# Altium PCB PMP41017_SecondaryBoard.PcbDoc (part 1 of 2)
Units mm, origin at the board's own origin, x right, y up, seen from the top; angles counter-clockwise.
Board outline 59.94 x 50.1 mm, 4 copper layers (Top Layer, Layer 1, Layer 2, Bottom Layer), stack 1.926 mm thick; 120 components, 60 nets, 831 pads, 509 vias.
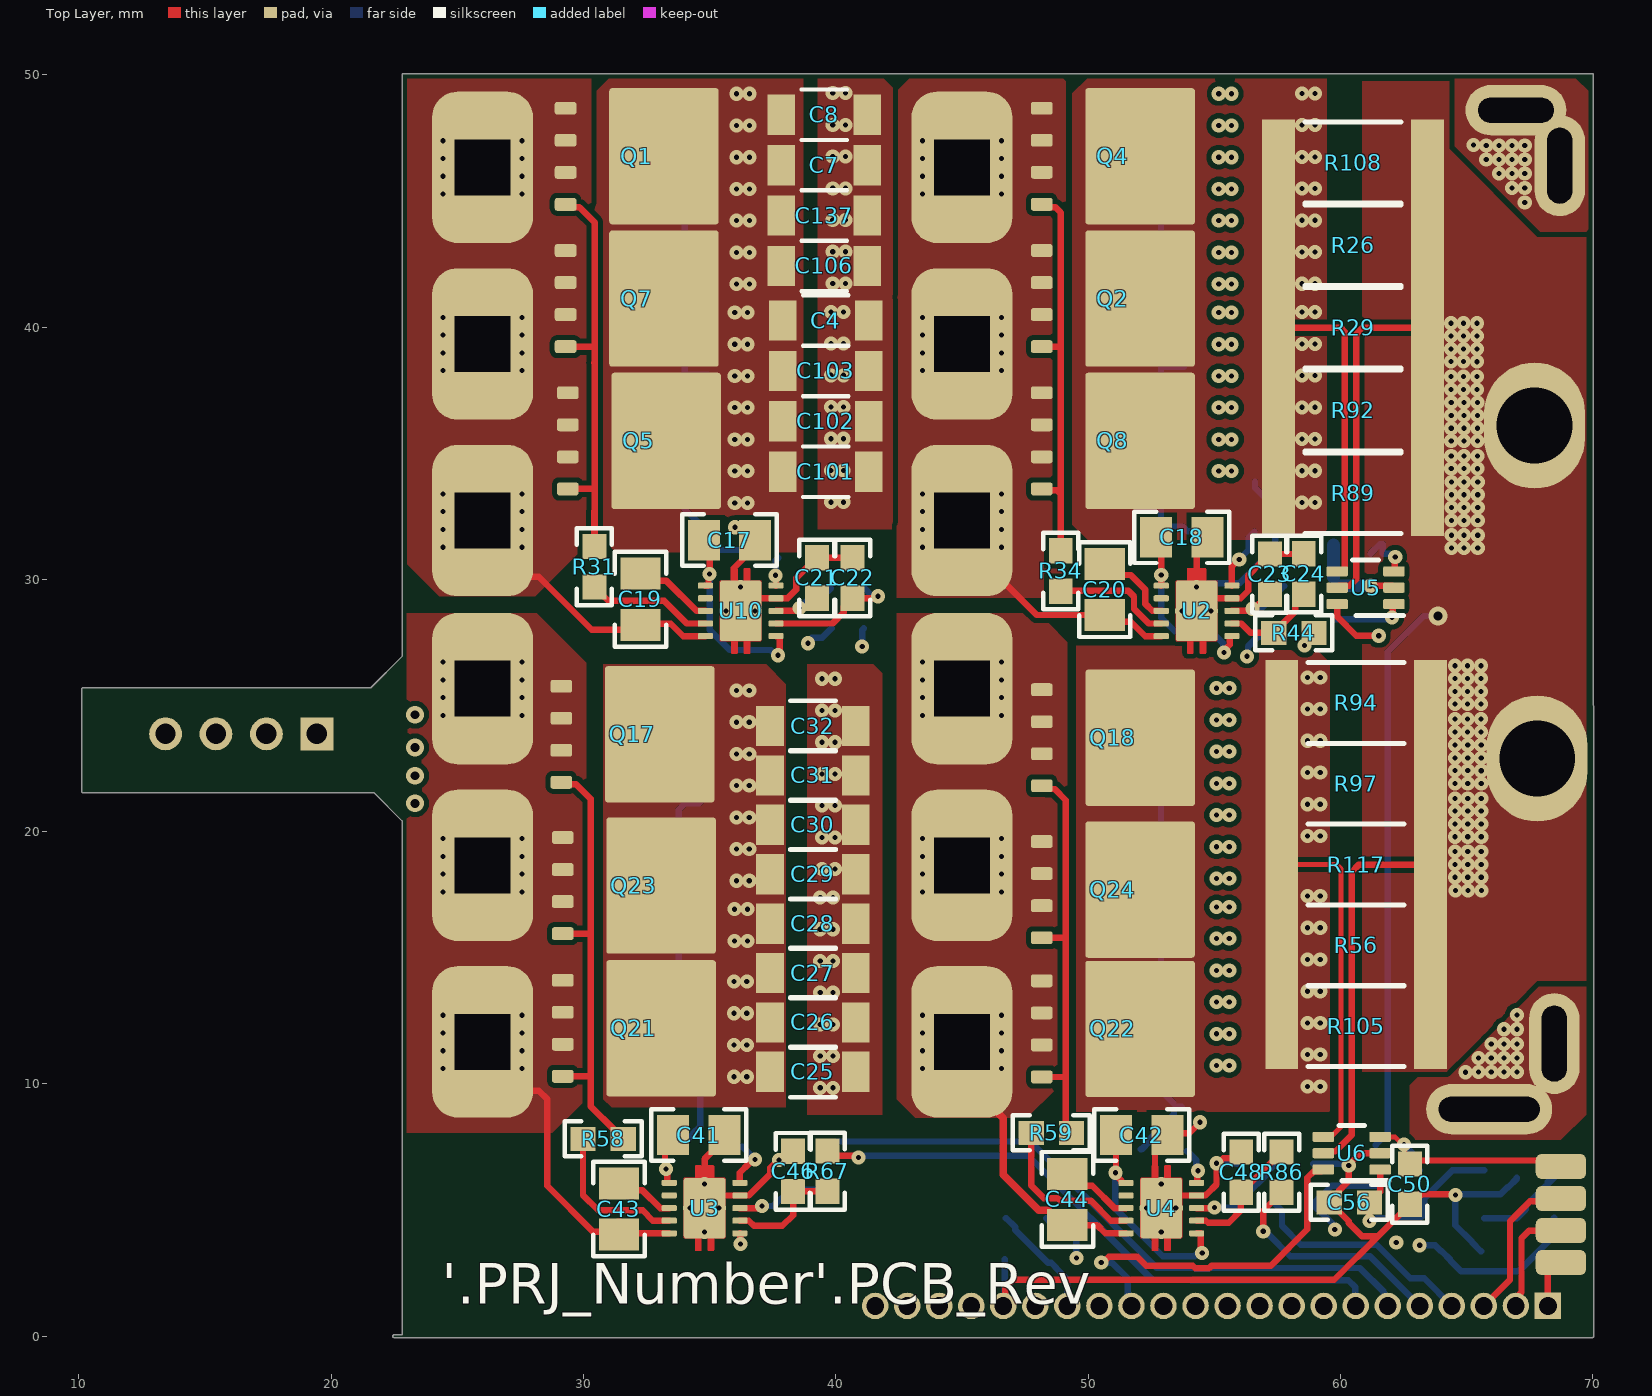
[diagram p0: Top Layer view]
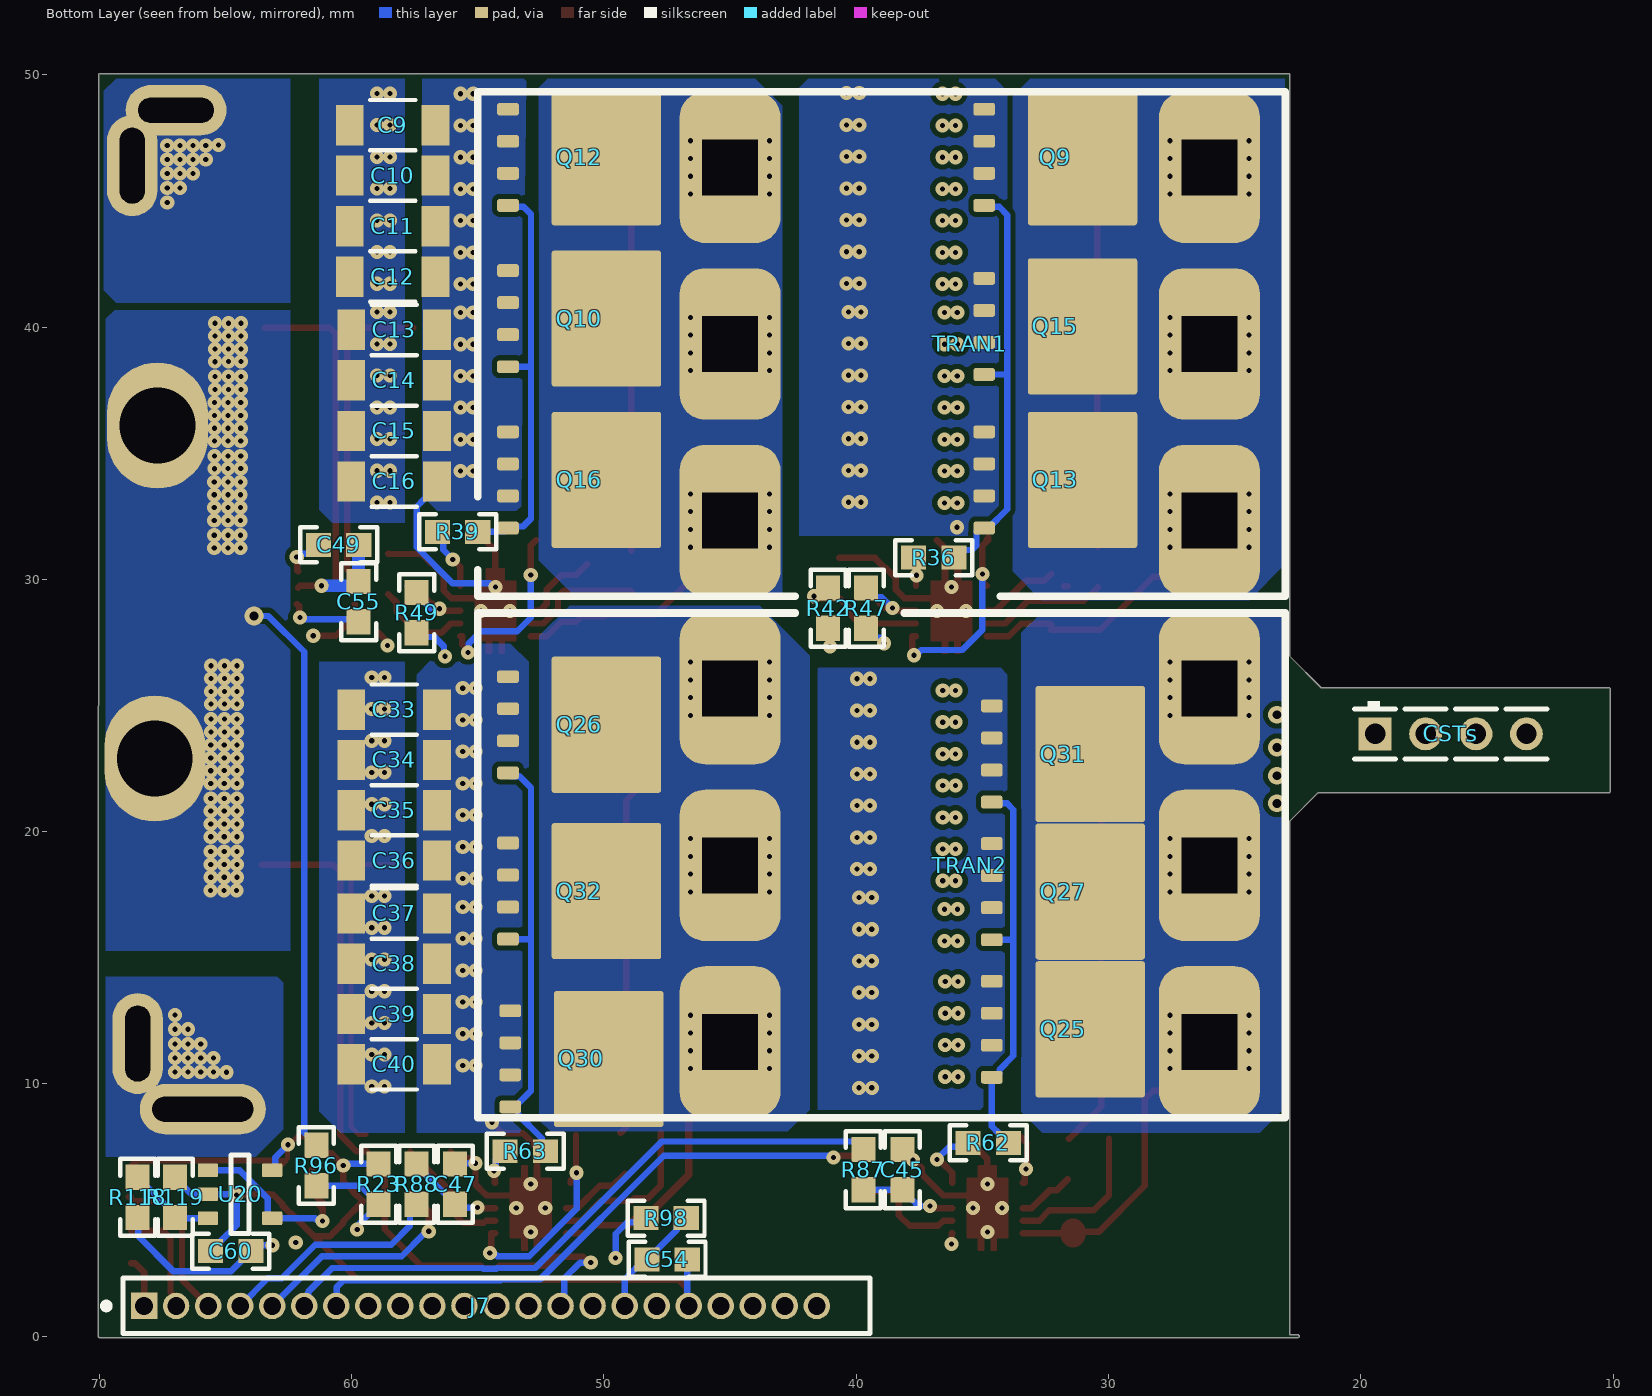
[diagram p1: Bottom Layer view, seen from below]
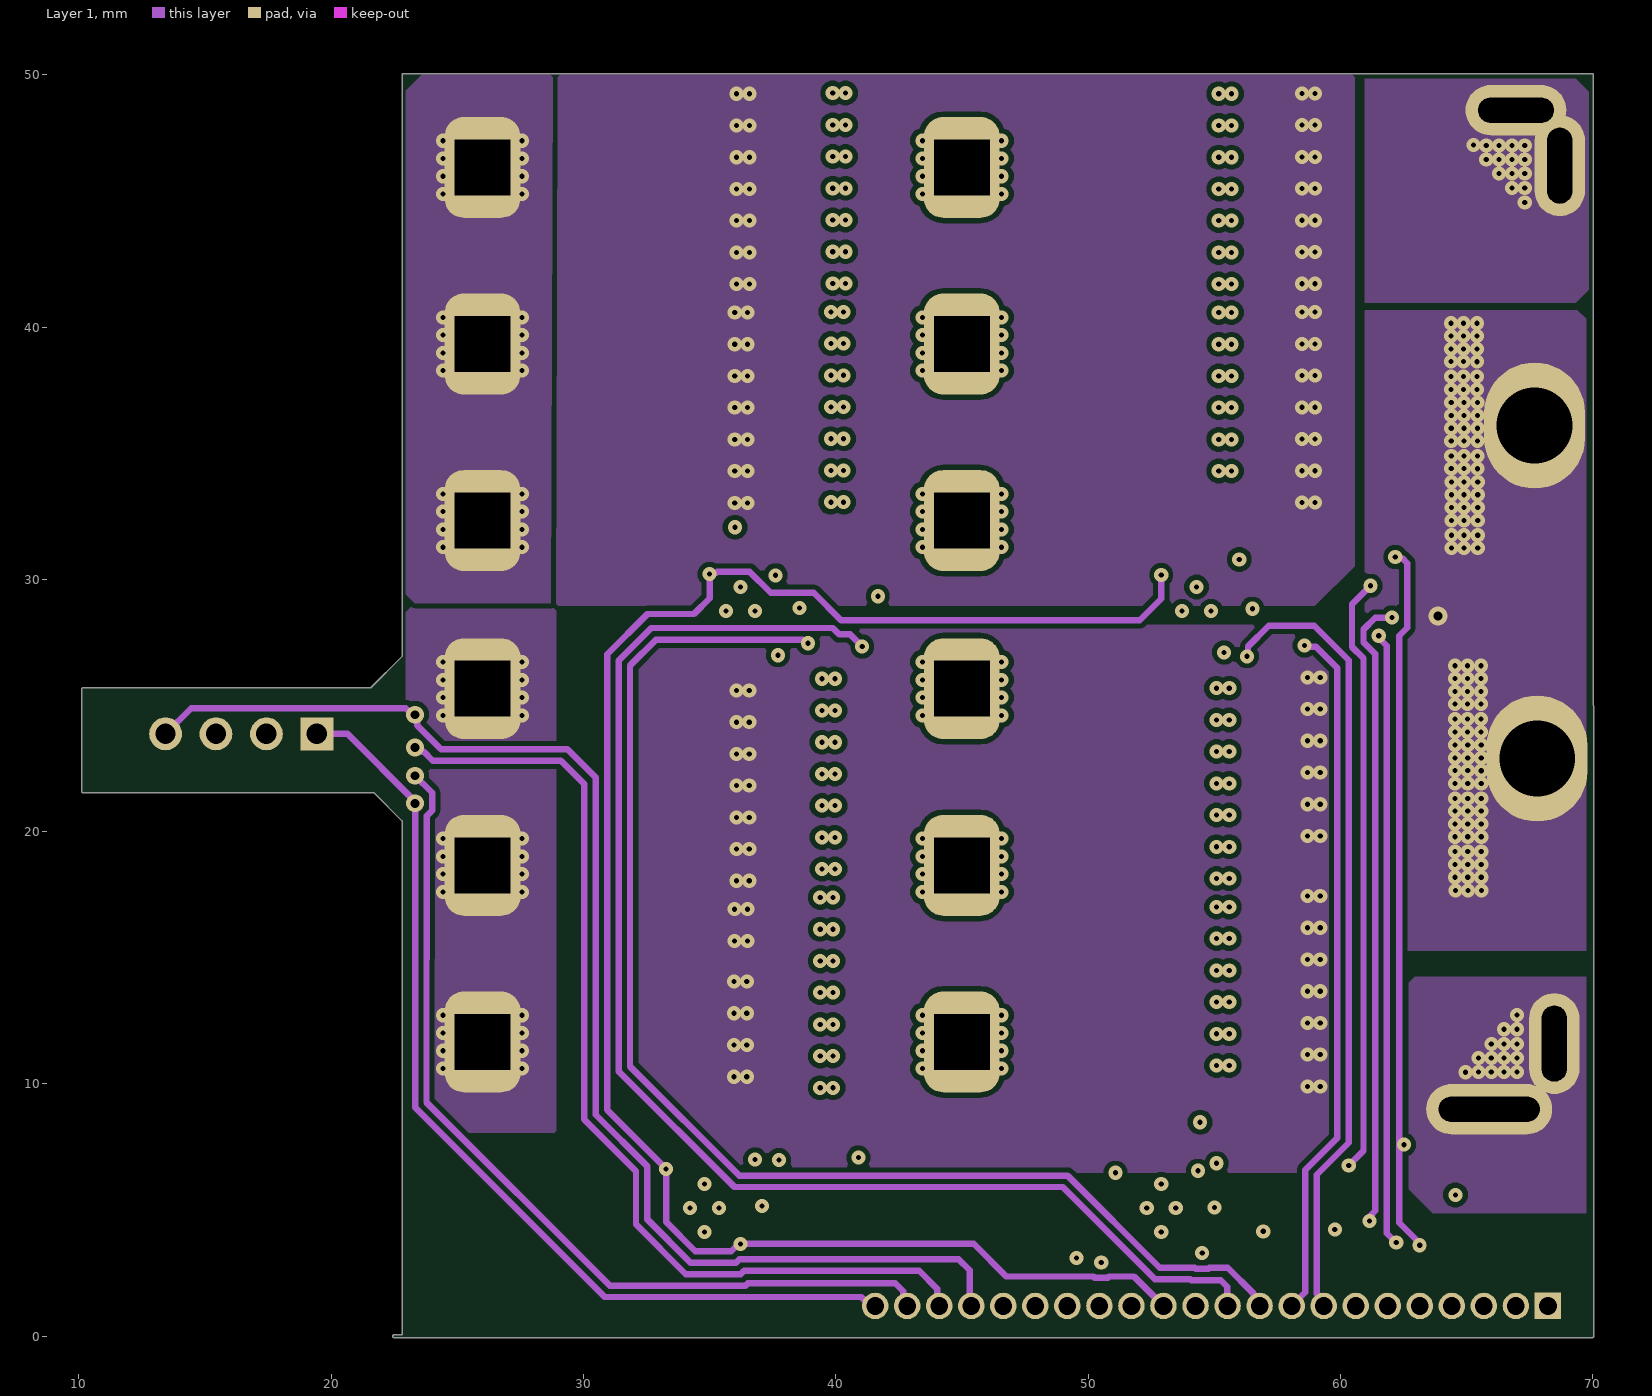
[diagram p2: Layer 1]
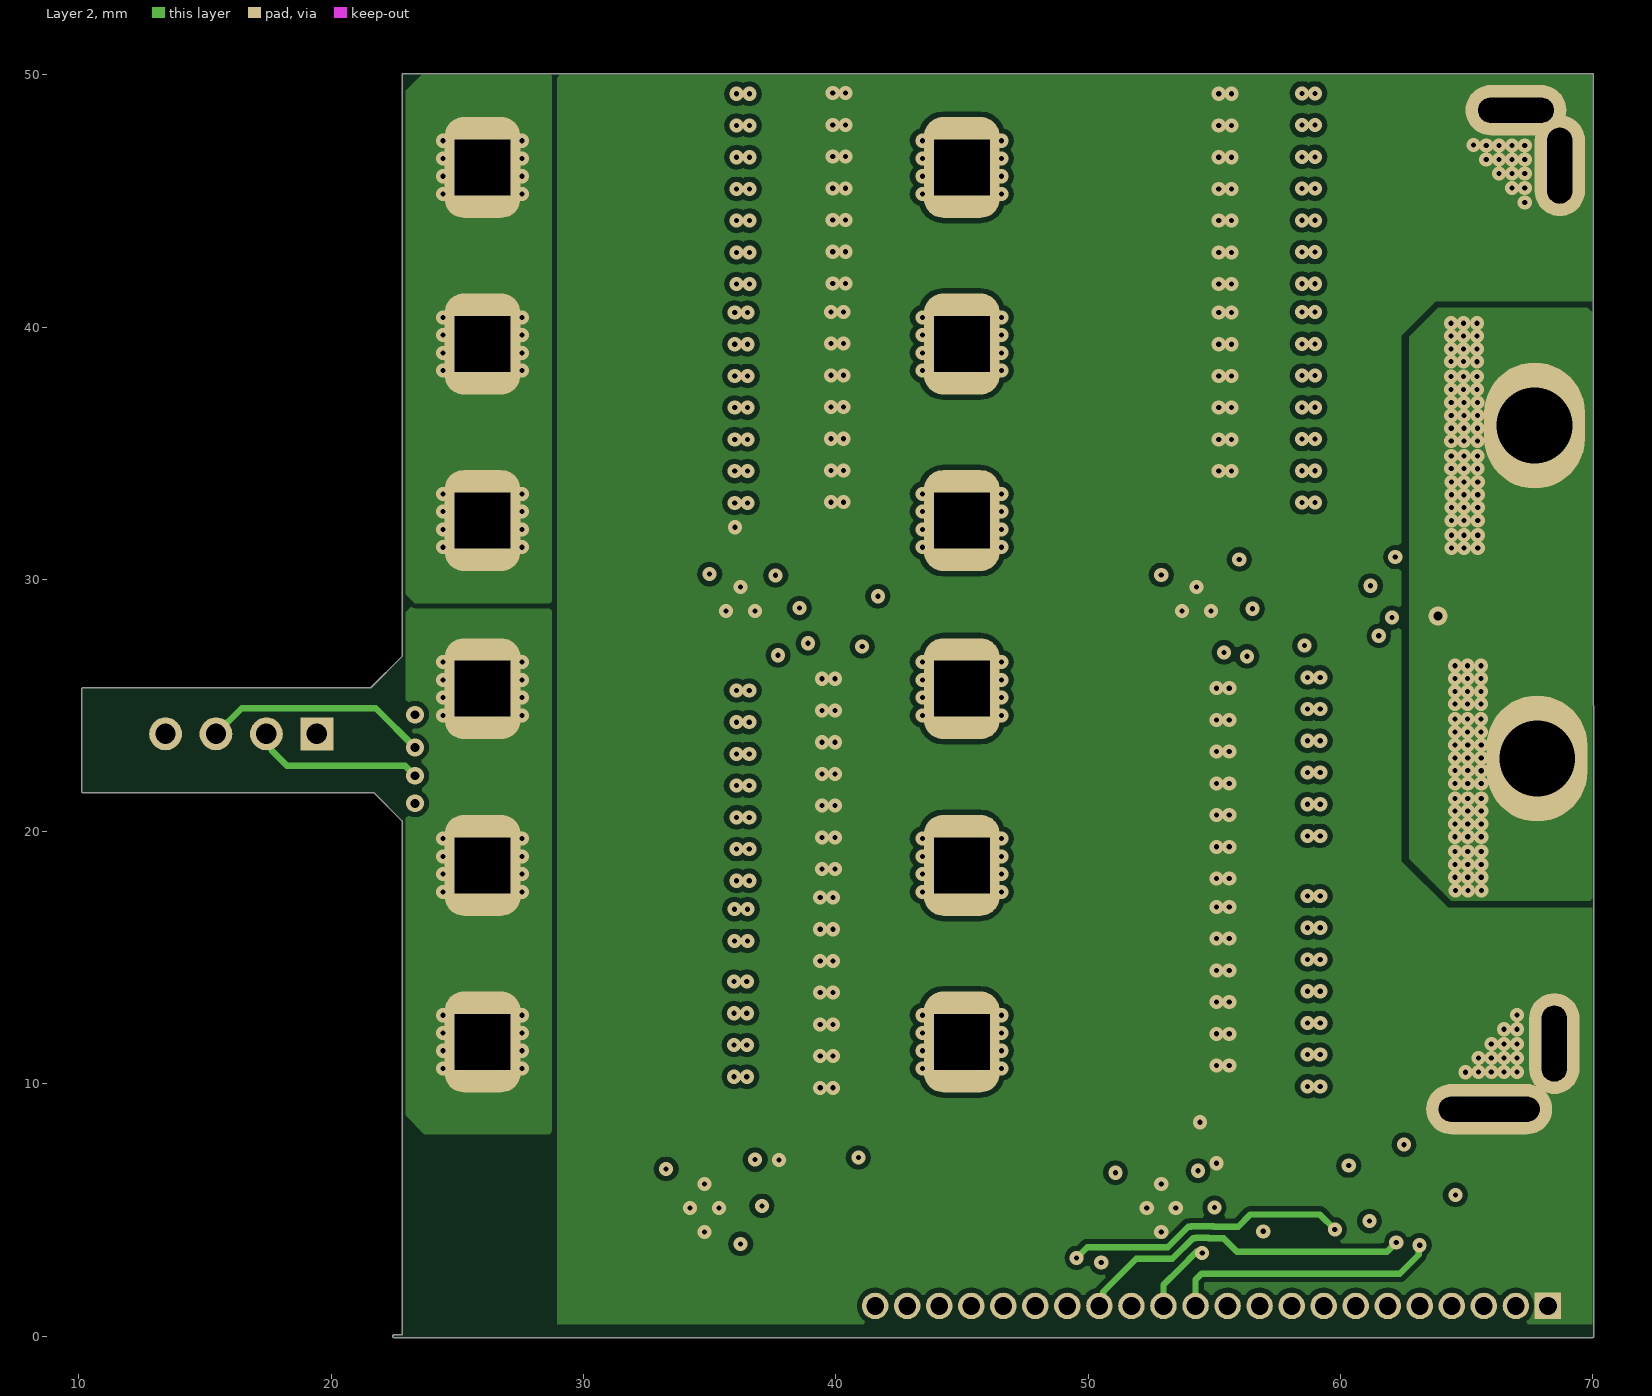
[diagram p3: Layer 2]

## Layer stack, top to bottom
Top Solder: solder mask 0.0102, Solder Resist, Dk 3.5
Top Layer: signal copper 0.07
Dielectric 1: prepreg 0.0711, PP-006, Dk 4.1
Layer 1: signal copper 0.07
Dielectric1: core 1.5037, FR-4 High Tg, Dk 4.8
Layer 2: signal copper 0.07
Dielectric 2: prepreg 0.0711, PP-006, Dk 4.1
Bottom Layer: signal copper 0.07
Bottom Solder: solder mask 0.0102, Solder Resist, Dk 3.5

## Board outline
22.479,-0.05 cw(c22.479,0) 22.479,0.05 22.81,0.05 22.81,20.426 21.696,21.54 10.16,21.54 cw(c10.16,21.59) 10.11,21.59 10.11,25.654 cw(c10.16,25.654) 10.16,25.704 21.569,25.704 22.81,26.945 22.81,50 cw(c22.86,50) 22.86,50.05 69.98,50.05 cw(c69.98,50) 70.031,50 70.05,0 cw(c70,0) 70,-0.05

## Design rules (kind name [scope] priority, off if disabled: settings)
AcuteAngle [All] p1: minimum=4.50000000000000E+0001 checktracksonly=TRUE
AssemblyTestPointUsage [All] p1: valid=2
BoardOutlineClearance BoardOutlineClearance_MountingHoles [OnCopper and InComponentClass('Mounting Holes')] p1 off: gap=0.2 ignorepadtopadclearanceinfootprint=FALSE
BoardOutlineClearance BoardOutlineClearance_Poly [OnCopper and IsPoly] p2 off: gap=0.2 ignorepadtopadclearanceinfootprint=FALSE
BoardOutlineClearance [OnCopper and Not InComponentClass('Logo') and not InComponentClass('FiducialMark') and not InRegion(1000,500,4000,800) and not InPoly] p3 off: gap=0.2 ignorepadtopadclearanceinfootprint=FALSE
Clearance Clearance_Keepouts [((IsTrack Or IsArc) And Not InPoly) And IsFree and IsKeepOut vs ((IsTrack Or IsArc) And Not InPoly) And IsFree and IsKeepOut] p1: gap=0 ignorepadtopadclearanceinfootprint=FALSE
Clearance Clearance_Poly [InPolygon] p2: gap=0.203 ignorepadtopadclearanceinfootprint=TRUE
Clearance Clearance_FiducialMark [IsKeepOut and InComponentClass('FiducialMark') vs IsPad and InComponentClass('FiducialMark')] p3: gap=0 ignorepadtopadclearanceinfootprint=FALSE
Clearance [All] p4: gap=0.2 ignorepadtopadclearanceinfootprint=TRUE
ComponentClearance ComponentClearance_MountingHoles_FiducialMarks [InComponentClass('Mounting Holes') vs InComponentClass('FiducialMark')] p1 off: gap=1.27 collisioncheckmode=3 verticalgap=0.254 showdistances=FALSE
ComponentClearance ComponentClearance_Shunt [InComponentClass('Header') vs InComponentClass('Shunt')] p2 off: gap=0 collisioncheckmode=3 verticalgap=0 showdistances=FALSE
ComponentClearance ComponentClearance_Logo [InComponentClass('Logo')] p3 off: gap=0.762 collisioncheckmode=3 verticalgap=0.254 showdistances=FALSE
ComponentClearance ComponentClearance_ScrewToNut [(HasFootprint('NY PMS 440 0025 PH')) vs (HasFootprint('Keystone_1902C'))] p4 off: gap=0.127 collisioncheckmode=3 verticalgap=0.254 showdistances=FALSE
ComponentClearance ComponentClearance_MountingHoles [InComponentClass('Mounting Holes')] p5 off: gap=2.54 collisioncheckmode=3 verticalgap=2540 showdistances=FALSE
ComponentClearance ComponentClearance_SmallPassives [HasFootprint('0201*') or HasFootprint('0402*') or HasFootprint('0508') or HasFootprint('0603*') or HasFootprint('0612') or HasFootprint('0805*') or HasFootprint('0815*') or HasFootprint('0830*') or HasFootprint('1206*') or HasFootprint('1210*') or HasFootprint('1808*') or HasFootprint('1812*') or HasFootprint('1825*') or HasFootprint('2010*') or HasFootprint('2220*') or HasFootprint('2225*') or HasFootprint('2512*') or HasFootprint('2728*') or HasFootprint('3518*') vs HasFootprint('0201*') or HasFootprint('0402*') or HasFootprint('0508') or HasFootprint('0603*') or HasFootprint('0612') or HasFootprint('0805*') or HasFootprint('0815*') or HasFootprint('0830*') or HasFootprint('1206*') or HasFootprint('1210*') or HasFootprint('1808*') or HasFootprint('1812*') or HasFootprint('1825*') or HasFootprint('2010*') or HasFootprint('2220*') or HasFootprint('2225*') or HasFootprint('2512*') or HasFootprint('2728*') or HasFootprint('3518*')] p6 off: gap=0.38 collisioncheckmode=3 verticalgap=0.254 showdistances=FALSE
ComponentClearance ComponentClearance_THtoSMT [IsThruComponent vs IsSMTComponent] p7 off: gap=0.762 collisioncheckmode=3 verticalgap=0.762 showdistances=FALSE
ComponentClearance ComponentClearance_THtoTH [IsThruComponent vs IsThruComponent] p8 off: gap=0.508 collisioncheckmode=3 verticalgap=0.762 showdistances=FALSE
ComponentClearance [All] p9 off: gap=0.508 collisioncheckmode=3 verticalgap=0.254 showdistances=FALSE
DiffPairsRouting [All] p1: maxlimit=2.54 minlimit=0.254 mostfreqgap=0.254 toplayer_minwidth=0.381 toplayer_maxwidth=0.381 toplayer_prefwidth=0.381 midlayer1_minwidth=0.381 midlayer1_maxwidth=0.381 midlayer1_prefwidth=0.381 midlayer2_minwidth=0.381 midlayer2_maxwidth=0.381 midlayer2_prefwidth=0.381 bottomlayer_minwidth=0.381 bottomlayer_maxwidth=0.381 bottomlayer_prefwidth=0.381 maxuncoupledlength=25.4
FabricationTestPointUsage TestPointUsage [All] p1: valid=2 allowmultiple=FALSE
FabricationTestpoint Testpoint [All] p1: side=3 testpointundercomponent=TRUE minsize=1.016 maxsize=2.54 preferedsize=1.524 minholesize=0 maxholesize=1.016 preferedholesize=0.813 testpointgrid=0.025 allowsidetop=TRUE allowsidebottom=TRUE usegrid=TRUE gridtolerance=0
FanoutControl Fanout_LCC [IsLCC] p1: bgadir=Out bgaviamode=Centered fanoutstyle=Auto fanoutdirection=Alternating viagrid=0.025 // Fanout_LCC (Default Rule)
FanoutControl Fanout_BGA [IsBGA] p2: bgadir=Out bgaviamode=Centered fanoutstyle=Auto fanoutdirection=Alternating viagrid=0.025 // Fanout_BGA (Default Rule)
FanoutControl Fanout_Default [All] p4: bgadir=Out bgaviamode=Centered fanoutstyle=Auto fanoutdirection=Alternating viagrid=0.025 // Fanout_Default (Default Rule)
FanoutControl Fanout_Small [(CompPinCount < 5)] p5: bgadir=Out bgaviamode=Centered fanoutstyle=Auto fanoutdirection=OutThenIn viagrid=0.025 // Fanout_Small (Default Rule)
Height [All] p1 off: minheight=0 maxheight=30 prefheight=12.7
HoleSize [All] p1: absolutevalues=TRUE maxlimit=6.375 minlimit=0.2 maxpercent=80.000 minpercent=20.000
MinimumAnnularRing MinimumAnnularRing_ThermalPadVias [IsVia and InAnyComponent] p1: minimumring=0.15
MinimumAnnularRing [All] p2: minimumring=0.152
MinimumSolderMaskSliver MinimumSolderMaskSliver_Logo [InComponentClass('Logo') vs InComponentClass('Logo')] p1: minsoldermaskwidth=0.018
MinimumSolderMaskSliver [All] p2: minsoldermaskwidth=0.1
PlaneConnect [All] p1: planeconnectstyle=Relief reliefexpansion=0.254 reliefentries=4 reliefconductorwidth=0.254 reliefairgap=0.254
PolygonConnect [All] p1: connectstyle=Direct reliefconductorwidth=0.254 reliefentries=4 polygonreliefangle="90 Angle" airgapwidth=0.254
RoutingVias ThermalPadVias [IsVia and InAnyComponent] p1: holewidth=0.2 width=0.5 viastyle="Through Hole" minholewidth=0.2 minwidth=0.5 maxholewidth=0.33 maxwidth=0.6
RoutingVias [All] p2: holewidth=0.3 width=0.508 viastyle="Through Hole" minholewidth=0.2 minwidth=0.5 maxholewidth=1.016 maxwidth=1.651
SilkToBoardRegionClearance [Not ((IsComment or IsDesignator) And (Hide <> 'False')) and not InRegion(1000,500,4000,800)] p1:
SilkToSilkClearance SilkToSilkClearance_Pb-FreeLogo [(HasFootprint('Pb-Free_Overlay_Medium') OR HasFootprint('Pb-Free_Overlay_Small')) vs (HasFootprint('Pb-Free_Overlay_Medium') OR HasFootprint('Pb-Free_Overlay_Small'))] p1: silktosilkclearance=0
SilkToSilkClearance [All] p2: silktosilkclearance=0
SilkToSolderMaskClearance SilkToComponentPadClearance [(IsPad or IsFill or IsRegion) and InAnycomponent] p1 off: minsilkscreentomaskgap=0.127 clearancetoexposedcopper=TRUE
SilkToSolderMaskClearance "Silk to Solder Mask Opening" [All] p2 off: minsilkscreentomaskgap=0.1 clearancetoexposedcopper=FALSE
SolderMaskExpansion [All] p1: expansion=0.05 istentingtop=FALSE
UnRoutedNet [All] p1: checkbadconnections=TRUE
Width [All] p1: maxlimit=2.54 minlimit=0.152 preferedwidth=0.254
13 further rules are at their usual default settings.

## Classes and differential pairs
component class Header: CSTs

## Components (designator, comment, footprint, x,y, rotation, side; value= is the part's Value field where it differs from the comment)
C4 "GMK316AB7106KL-TR" 1206_190 39.602,40.262 r0 top value=10uF
C7 "GMK316AB7106KL-TR" 1206_190 39.543,46.422 r0 top value=10uF
C8 "GMK316AB7106KL-TR" 1206_190 39.543,48.421 r0 top value=10uF
C9 "GMK316AB7106KL-TR" 1206_190 58.372,48.006 r180 bottom value=10uF
C10 "GMK316AB7106KL-TR" 1206_190 58.372,46.01 r180 bottom value=10uF
C11 "GMK316AB7106KL-TR" 1206_190 58.372,44.007 r180 bottom value=10uF
C12 "GMK316AB7106KL-TR" 1206_190 58.372,42.003 r180 bottom value=10uF
C13 "GMK316AB7106KL-TR" 1206_190 58.318,39.893 r180 bottom value=10uF
C14 "GMK316AB7106KL-TR" 1206_190 58.318,37.889 r180 bottom value=10uF
C15 "GMK316AB7106KL-TR" 1206_190 58.318,35.886 r180 bottom value=10uF
C16 "GMK316AB7106KL-TR" 1206_190 58.318,33.883 r180 bottom value=10uF
C17 "C2012X7R1V475K125AC" 0805_HV 35.789,31.56 r0 top value=4.7uF
C18 "C2012X7R1V475K125AC" 0805_HV 53.715,31.667 r0 top value=4.7uF
C19 "C2012X7R1V475K125AC" 0805_HV 32.258,29.21 r270 top value=4.7uF
C20 "C2012X7R1V475K125AC" 0805_HV 50.666,29.597 r270 top value=4.7uF
C21 "CGA3E2C0G1H101J080AA" 0603 39.246,30.058 r270 top value=100pF
C22 "CGA3E2C0G1H101J080AA" 0603 40.666,30.058 r270 top value=100pF
C23 "CGA3E2C0G1H101J080AA" 0603 57.205,30.208 r270 top value=100pF
C24 "CGA3E2C0G1H101J080AA" 0603 58.55,30.216 r270 top value=100pF
C25 "GMK316AB7106KL-TR" 1206_190 39.095,10.479 r0 top value=10uF
C26 "GMK316AB7106KL-TR" 1206_190 39.095,12.437 r0 top value=10uF
C27 "GMK316AB7106KL-TR" 1206_190 39.095,14.396 r0 top value=10uF
C28 "GMK316AB7106KL-TR" 1206_190 39.095,16.354 r0 top value=10uF
C29 "GMK316AB7106KL-TR" 1206_190 39.095,18.313 r0 top value=10uF
C30 "GMK316AB7106KL-TR" 1206_190 39.095,20.271 r0 top value=10uF
C31 "GMK316AB7106KL-TR" 1206_190 39.095,22.23 r0 top value=10uF
C32 "GMK316AB7106KL-TR" 1206_190 39.095,24.189 r0 top value=10uF
C33 "GMK316AB7106KL-TR" 1206_190 58.318,24.838 r180 bottom value=10uF
C34 "GMK316AB7106KL-TR" 1206_190 58.318,22.844 r180 bottom value=10uF
C35 "GMK316AB7106KL-TR" 1206_190 58.318,20.851 r180 bottom value=10uF
C36 "GMK316AB7106KL-TR" 1206_190 58.318,18.857 r180 bottom value=10uF
C37 "GMK316AB7106KL-TR" 1206_190 58.318,16.759 r180 bottom value=10uF
C38 "GMK316AB7106KL-TR" 1206_190 58.318,14.765 r180 bottom value=10uF
C39 "GMK316AB7106KL-TR" 1206_190 58.318,12.772 r180 bottom value=10uF
C40 "GMK316AB7106KL-TR" 1206_190 58.318,10.778 r180 bottom value=10uF
C41 "C2012X7R1V475K125AC" 0805_HV 34.566,7.975 r0 top value=4.7uF
C42 "C2012X7R1V475K125AC" 0805_HV 52.127,7.975 r0 top value=4.7uF
C43 "C2012X7R1V475K125AC" 0805_HV 31.407,5.043 r270 top value=4.7uF
C44 "C2012X7R1V475K125AC" 0805_HV 49.18,5.423 r270 top value=4.7uF
C45 "CGA3E2C0G1H101J080AA" 0603 38.173,6.604 r270 bottom value=100pF
C46 "CGA3E2C0G1H101J080AA" 0603 38.31,6.532 r270 top value=100pF
C47 "CGA3E2C0G1H101J080AA" 0603 55.895,6.03 r270 bottom value=100pF
C48 "CGA3E2C0G1H101J080AA" 0603 56.073,6.505 r270 top value=100pF
C49 "C1608X7R1E104K080AA" 0603 60.516,31.372 r180 bottom value=0.1uF
C50 "C1608X7R1E104K080AA" 0603 62.758,6.03 r270 top value=0.1uF
C54 "C0603C471K5RACTU" 0603 47.498,3.048 r180 bottom value=470pF
C55 "C1608X7R1E104K080AA" 0603 59.724,29.12 r270 bottom value=0.1uF
C56 "C1608X7R1E104K080AA" 0603 60.356,5.307 r0 top value=0.1uF
C60 "C1608X7R1E104K080AA" 0603 64.793,3.371 r180 bottom value=0.1uF
C101 "GMK316AB7106KL-TR" 1206_190 39.602,34.266 r0 top value=10uF
C102 "GMK316AB7106KL-TR" 1206_190 39.602,36.265 r0 top value=10uF
C103 "GMK316AB7106KL-TR" 1206_190 39.602,38.263 r0 top value=10uF
C106 "GMK316AB7106KL-TR" 1206_190 39.543,42.425 r0 top value=10uF
C137 "GMK316AB7106KL-TR" 1206_190 39.543,44.423 r0 top value=10uF
CSTs "PTT-104-01-L-S" Samtec_PTT-104-01-x-S 16.431,23.876 r180 bottom
J7 "M52-5002345" M52-5012345 68.23,1.2 r180 bottom locked
Q1 "CSD17573Q5B" DNK0008A#1 32.109,46.772 r0 top value=30V
Q2 "CSD17573Q5B" DNK0008A#1 50.983,41.133 r0 top value=30V
Q4 "CSD17573Q5B" DNK0008A#1 50.983,46.772 r0 top value=30V
Q5 "CSD17573Q5B" DNK0008A#1 32.196,35.493 r0 top value=30V
Q7 "CSD17573Q5B" DNK0008A#1 32.109,41.133 r0 top value=30V
Q8 "CSD17573Q5B" DNK0008A#1 50.983,35.493 r0 top value=30V
Q9 "CSD17573Q5B" DNK0008A#2 32.109,46.732 r180 bottom value=30V
Q10 "CSD17573Q5B" DNK0008A#2 50.983,40.337 r180 bottom value=30V
Q12 "CSD17573Q5B" DNK0008A#2 50.983,46.732 r180 bottom value=30V
Q13 "CSD17573Q5B" DNK0008A#2 32.109,33.943 r180 bottom value=30V
Q15 "CSD17573Q5B" DNK0008A#2 32.109,40.028 r180 bottom value=30V
Q16 "CSD17573Q5B" DNK0008A#2 50.983,33.943 r180 bottom value=30V
Q17 "CSD17573Q5B" DNK0008A#1 31.942,23.861 r0 top value=30V
Q18 "CSD17573Q5B" DNK0008A#1 50.986,23.724 r0 top value=30V
Q21 "CSD17573Q5B" DNK0008A#1 31.996,12.206 r0 top value=30V
Q22 "CSD17573Q5B" DNK0008A#1 50.983,12.182 r0 top value=30V
Q23 "CSD17573Q5B" DNK0008A#1 31.996,17.864 r0 top value=30V
Q24 "CSD17573Q5B" DNK0008A#1 50.983,17.702 r0 top value=30V
Q25 "CSD17573Q5B" DNK0008A#2 31.802,12.168 r180 bottom value=30V
Q26 "CSD17573Q5B" DNK0008A#2 50.983,24.238 r180 bottom value=30V
Q27 "CSD17573Q5B" DNK0008A#2 31.802,17.623 r180 bottom value=30V
Q30 "CSD17573Q5B" DNK0008A#2 50.89,10.995 r180 bottom value=30V
Q31 "CSD17573Q5B" DNK0008A#2 31.802,23.079 r180 bottom value=30V
Q32 "CSD17573Q5B" DNK0008A#2 50.983,17.648 r180 bottom value=30V
R23 "RC0603FR-075K1L" 0603 58.928,6.03 r270 bottom value=5.10k
R26 "CSNL2512FTL500" 2512 60.503,43.248 r180 top value=0.0005
R29 "CSNL2512FTL500" 2512 60.503,39.973 r180 top value=0.0005
R31 "ERJ-3RQF2R2V" 0603 30.43,30.503 r90 top value=2.20
R34 "ERJ-3RQF2R2V" 0603 48.917,30.334 r90 top value=2.20
R36 "ERJ-3RQF2R2V" 0603 36.926,30.864 r180 bottom value=2.20
R39 "ERJ-3RQF2R2V" 0603 55.8,31.884 r180 bottom value=2.20
R42 "RC0603FR-07100RL" 0603 41.115,28.864 r90 bottom value=100
R44 "RC0603FR-07100RL" 0603 58.158,27.879 r180 top value=100
R47 "RC0603FR-07100RL" 0603 39.603,28.864 r90 bottom value=100
R49 "RC0603FR-07100RL" 0603 57.427,28.683 r90 bottom value=100
R56 "CSNL2512FTL500" 2512 60.625,15.494 r180 top value=0.0005
R58 "ERJ-3RQF2R2V" 0603 30.778,7.823 r0 top value=2.20
R59 "ERJ-3RQF2R2V" 0603 48.547,8.059 r0 top value=2.20
R62 "ERJ-3RQF2R2V" 0603 34.766,7.662 r180 bottom value=2.20
R63 "ERJ-3RQF2R2V" 0603 53.117,7.332 r180 bottom value=2.20
R67 "RC0603FR-07100RL" 0603 39.663,6.543 r270 top value=100
R86 "RC0603FR-07100RL" 0603 57.675,6.505 r90 top value=100
R87 "RC0603FR-07100RL" 0603 39.716,6.604 r270 bottom value=100
R88 "RC0603FR-07100RL" 0603 57.427,6.03 r90 bottom value=100
R89 "CSNL2512FTL500" 2512 60.503,33.422 r180 top value=0.0005
R92 "CSNL2512FTL500" 2512 60.503,36.697 r180 top value=0.0005
R94 "CSNL2512FTL500" 2512 60.625,25.102 r180 top value=0.0005
R96 "RC0603FR-0720KL" 0603 61.403,6.767 r270 bottom value=20.0k
R97 "CSNL2512FTL500" 2512 60.625,21.899 r180 top value=0.0005
R98 "RC0603FR-07100RL" 0603 47.538,4.679 r180 bottom value=100
R105 "CSNL2512FTL500" 2512 60.625,12.291 r180 top value=0.0005
R108 "CSNL2512FTL500" 2512 60.503,46.524 r180 top value=0.0005
R117 "CSNL2512FTL500" 2512 60.625,18.696 r180 top value=0.0005
R118 "RC0603FR-075K1L" 0603 68.481,5.503 r270 bottom value=5.10k
R119 "RC0603FR-07100RL" 0603 67.001,5.503 r270 bottom value=100
TRAN1 "PQ32" PQ3220-1500-400V12V_sec 38.997,39.333 r0 bottom
TRAN2 "PQ32" PQ3220-1500-400V12V_sec 38.999,18.668 r0 bottom
U2 "UCC27282DRCR" DRC0010J 54.302,28.753 r0 top
U3 "UCC27282DRCR" DRC0010J 34.798,5.08 r0 top
U4 "UCC27282DRCR" DRC0010J 52.902,5.08 r0 top
U5 "INA210BIDCKR" DCK0006A_N 61,29.67 r180 top
U6 "INA210BIDCKR" DCK0006A_N 60.451,7.255 r180 top
U10 "UCC27282DRCR" DRC0010J 36.23,28.753 r0 top
U20 "TS321IDBVR" DBV0005A_L 64.425,5.629 r180 bottom

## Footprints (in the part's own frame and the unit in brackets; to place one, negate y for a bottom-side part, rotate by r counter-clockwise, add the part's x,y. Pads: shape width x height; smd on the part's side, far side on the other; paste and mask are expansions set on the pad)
0603 [mm] "0603 from SM-752 data"
  rect 1x0.95 smd: 1(-0.8,0) 2(0.8,0)
  silkscreen extent -1.52,-0.69 1.52,0.69, body extent -0.87,-0.47 0.87,0.47, height 1
0805_HV [mil] "0805 with 30mil clearance between pads"
  rect 50x63 smd: 1(-40,0) 2(40,0)
  silkscreen extent -74,-40 74,40, body extent -43,-29 43,29, height 57
1206_190 [mm] "1206_190"
  rect 1.1x1.6 smd: 1(-1.7,0) 2(1.7,0)
  silkscreen extent -0.9,-1 0.9,1, body extent -1.75,-0.95 1.75,0.95, height 1.9
2512 [mm] "Chip Resistor, Body 6.3x3.2mm, IPC Medium Density"
  rect 1.3x3.4 smd: 1(-2.95,0) 2(2.95,0)
  silkscreen extent -1.9,-1.6 1.9,1.6, body extent -3.22,-1.67 3.22,1.67, height 0.71
DBV0005A_L [mm] "SOT23, 5-Leads, Body 2.9x1.6mm, Pitch 0.95mm, Lead Span 2.8mm, IPC High Density"
  rrect18% 0.8x0.55 smd: 1(-1.275,0.95) 2(-1.275,0) 3(-1.275,-0.95) 4(1.275,-0.95) 5(1.275,0.95)
  silkscreen extent -0.35,-1.55 0.35,1.55, body extent -1.42,-1.46 1.42,1.46, height 1.09
DCK0006A_N [mm] "SOT23, 6-Leads, Body 2x1.3mm, Pitch 0.65mm, Lead Span 2.1mm, IPC Medium Density"
  rrect25% 0.85x0.4 smd: 1(-1.125,0.65) 2(-1.125,0) 3(-1.125,-0.65) 4(1.125,-0.65) 5(1.125,0) 6(1.125,0.65)
  silkscreen extent -1.5,-1.09 0.51,1.09, body extent -1.14,-1 1.14,1, height 0.95
DNK0008A#1 [mm] "SON, 8-Leads, Body 5x6mm"
  rrect39% 0.86x0.51 smd paste-0.05 mask-0.05: 1(-2.82,1.905) 2(-2.82,0.635) 3(-2.82,-0.635) 4(-2.82,-1.905) 5(2.82,-1.905) 6(2.82,-0.635) 7(2.82,0.635) 8(2.82,1.905)
  rrect40% 0.25x0.555 on Top Paste: 9(-0.83,-2.372) 9(-0.83,2.372)
  rrect40% 0.25x0.555 on Top Solder: 9(-0.83,-2.372) 9(-0.83,2.372)
  rrect11% 0.95x1.13 on Top Paste: 9(-0.535,-1.33) 9(-0.535,0) 9(-0.535,1.33) 9(0.615,-1.33) 9(0.615,0) 9(0.615,1.33) 9(1.765,-1.33) 9(1.765,0) 9(1.765,1.33)
  rrect3% 3.58x4 on Top Solder: 9(0.75,0)
  rrect5% 4.34x5.4 smd paste-3 mask-3: 9(1.08,0)
  body extent -3.05,-2.55 3.05,2.55, height 1.06
DNK0008A#2 [mm] "SON, 8-Leads, Body 5x6mm"
  rrect39% 0.86x0.51 smd paste-0.05 mask-0.05: 1(-2.82,1.905) 2(-2.82,0.635) 3(-2.82,-0.635) 4(-2.82,-1.905) 5(2.82,-1.905) 6(2.82,-0.635) 7(2.82,0.635) 8(2.82,1.905)
  rrect40% 0.25x0.555 on Bottom Paste: 9(-0.83,-2.372) 9(-0.83,2.372)
  rrect40% 0.25x0.555 on Bottom Solder: 9(-0.83,-2.372) 9(-0.83,2.372)
  rrect11% 0.95x1.13 on Bottom Paste: 9(-0.535,-1.33) 9(-0.535,0) 9(-0.535,1.33) 9(0.615,-1.33) 9(0.615,0) 9(0.615,1.33) 9(1.765,-1.33) 9(1.765,0) 9(1.765,1.33)
  rrect3% 3.58x4 on Bottom Solder: 9(0.75,0)
  rrect5% 4.34x5.4 smd paste-3 mask-3: 9(1.08,0)
  body extent -3.05,-2.55 3.05,2.55, height 1.06
DRC0010J [mm] "VSON-10"
  rrect42% 0.6x0.24 smd: 1(-1.4,1) 2(-1.4,0.5) 3(-1.4,0) 4(-1.4,-0.5) 5(-1.4,-1) 6(1.4,-1) 7(1.4,-0.5) 8(1.4,0) 9(1.4,0.5) 10(1.4,1)
  rrect12% 1.65x2.4 smd paste-1 mask-2: 11(0,0)
  Top Layer region: -0.375,-1.65 -0.375,-1.2 -0.775,-1.2 -0.794,-1.196 -0.81,-1.185 -0.821,-1.169 -0.825,-1.15 -0.825,-1.15 -0.825,1.15 -0.821,1.169 -0.81,1.185 -0.794,1.196 -0.775,1.2 -0.775,1.2 -0.375,1.2 -0.375,1.65 -0.371,1.669 -0.36,1.685 -0.344,1.696 -0.325,1.7 -0.325,1.7 -0.325,1.7 -0.175,1.7 -0.175,1.7 -0.156,1.696 -0.14,1.685 -0.129,1.669 -0.125,1.65 -0.125,1.65 -0.125,1.2 0.125,1.2 0.125,1.65 0.129,1.669 0.14,1.685 0.156,1.696 0.175,1.7 0.175,1.7 0.175,1.7 0.325,1.7 0.325,1.7 0.344,1.696 0.36,1.685 0.371,1.669 0.375,1.65 0.375,1.65 0.375,1.2 0.775,1.2 0.794,1.196 0.81,1.185 0.821,1.169 0.825,1.15 0.825,1.15 0.825,-1.15 0.821,-1.169 0.81,-1.185 0.794,-1.196 0.775,-1.2 0.775,-1.2 0.375,-1.2 0.375,-1.65 0.371,-1.669 0.36,-1.685 0.344,-1.696 0.325,-1.7 0.325,-1.7 0.175,-1.7 0.156,-1.696 0.14,-1.685 0.129,-1.669 0.125,-1.65 0.125,-1.65 0.125,-1.2 -0.125,-1.2 -0.125,-1.65 -0.129,-1.669 -0.14,-1.685 -0.156,-1.696 -0.175,-1.7 -0.175,-1.7 -0.325,-1.7 -0.344,-1.696 -0.36,-1.685 -0.371,-1.669 -0.375,-1.65
  body extent -1.5,-1.5 1.5,1.5, height 1
M52-5012345 [mm] "CONN RCPT 23POS 0.05 GOLD PCB"
  rect 1.05x1.05 hole 0.7: 1(0,0)
  round 1.05 hole 0.7: 2(1.27,0) 3(2.54,0) 4(3.81,0) 5(5.08,0) 6(6.35,0) 7(7.62,0) 8(8.89,0) 9(10.16,0) 10(11.43,0) 11(12.7,0) 12(13.97,0) 13(15.24,0) 14(16.51,0) 15(17.78,0) 16(19.05,0) 17(20.32,0) 18(21.59,0) 19(22.86,0) 20(24.13,0) 21(25.4,0) 22(26.67,0)
  silkscreen extent -1.6,-1.1 28.78,1.1, body extent -0.3,-0.3 0.3,0.3, height 4.1
PQ3220-1500-400V12V_sec [mm] "1500W Transformer from 400V to 12V with PQ3220 Core"
  rrect50% 4x6 / inner rrect50% 3x4 / far side rrect50% 4x6 hole 2.2 square: 5(-13,-7) 5(-13,0) 5(-13,7) 6(6,-7) 6(6,0) 6(6,7)
  silkscreen extent -16,-10 16,10
Samtec_PTT-104-01-x-S [mm] "Header, 2mm, 4x1, TH"
  rect 1.3x1.3 hole 0.81: 1(-3,0)
  round 1.3 hole 0.81: 2(-1,0) 3(1,0) 4(3,0)
  silkscreen extent -3.81,-0.99 3.81,1.3, body extent -4,-0.99 4,0.99, height 4.7

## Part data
C4 C7 C8 C9 C10 C11 C12 C13 C14 C15 C16 C25 C26 C27 C28 C29 C30 C31 C32 C33 C34 C35 C36 C37 C38 C39 C40 C101 C102 C103 C106 C137: library part CMP-0008822-2, "CAP, CERM, 10 uF, 35 V, +/- 10%, X7R, 1206_190", Cap_Case=1206, Manufacturer="Taiyo Yuden", Supplier Part Number 1=587-3007-1-ND, TempCo=X7R, Tolerance_%=10%, Value1=Unknown, Value2=35V, ValueDisplayed=10uF
C17 C18 C19 C20 C41 C42 C43 C44: library part CMP-0007885-2, "CAP, CERM, 4.7 uF, 35 V, +/- 10%, X7R, 0805", Cap_Case=0805, Manufacturer=TDK, Supplier Part Number 1=445-7555-1-ND, TempCo=X7R, Tolerance_%=10%, Value1="0.002346 ohm", Value2=35V, ValueDisplayed=4.7uF
C21 C22 C23 C24 C45 C46 C47 C48: library part CMP-0006751-4, "CAP, CERM, 100 pF, 25 V, +/- 10%, X7R, 0603", Cap_Case=0603, Manufacturer=Samsung, PartNumber=CL10B101KB8NNNC, Supplier Part Number 1=1276-1909-2-ND, TempCo=X7R, Tolerance_%=10%, Value1=Unknown, Value2=25V, ValueDisplayed=100pF
C49 C50 C55 C56 C60: library part CMP-0007039-5, "CAP, CERM, 0.1 uF, 25 V, +/- 10%, X7R, 0603", Cap_Case=0603, Manufacturer=TDK, Supplier Part Number 1=445-1316-1-ND, TempCo=X7R, Tolerance_%=10%, Value1=Unknown, Value2=25V, ValueDisplayed=0.1uF
C54: library part CMP-0007455-4, "CAP, CERM, 470 pF, 50 V, +/- 10%, X7R, 0603", Cap_Case=0603, Manufacturer=KEMET, Supplier Part Number 1=399-1075-1-ND, TempCo=X7R, Tolerance_%=10%, Value1=Unknown, Value2=50V, ValueDisplayed=470pF
CSTs: library part CMP-0055572-1, "Header, 2mm, 4x1, Gold, TH", Color=Black, Current_A=2.9A, Manufacturer=Samtec
J7: library part Receptacle_23x1, "Receptacle, 23x1, 1.27mm, TH", Manufacturer="Harwin Inc.", Supplier Part Number 1=855-M52-5012345
Q1 Q2 Q4 Q5 Q7 Q8 Q9 Q10 Q12 Q13 Q15 Q16 Q17 Q18 Q21 Q22 Q23 Q24 Q25 Q26 Q27 Q30 Q31 Q32: library part CMP-0000586-2, "MOSFET, N-CH, 30 V, 100 A, DNK0008A (VSON-CLIP-8)", Alternate Manufacturer=None, Manufacturer="Texas Instruments", Supplier Part Number 1=CSD17573Q5B-ND, Value1=0.0014, Value2="49 nC"
R23 R118: library part CMP-0023198-5, "RES, 5.10 k, 1%, 0.1 W, 0603", Manufacturer=Yageo, Power_W=100mW, Supplier Part Number 1=311-5.10KHRCT-ND, TempCo="100 ppm/C", Tolerance_%=1%, Value2=0.1W, Value_Code=5k10, ValueDisplayed=5.10k
R26 R29 R56 R89 R92 R94 R97 R105 R108 R117: library part CMP-0015817-2, "RES, 0.0005, 1%, 2 W, 2512", Manufacturer="Stackpole Electronics Inc", Power_W=3W, TempCo=ppm/C, Tolerance_%=1%, Value2=2W, Value_Code=1L000, ValueDisplayed=0.0005
R31 R34 R36 R39 R58 R59: library part CMP-0022711-2, "RES, 1ohm 1%, 0.1 W, 0603", Manufacturer=Panasonic, Power_W=100mW, TempCo="200 ppm/C", Tolerance_%=1%, Value2=0.1W, Value_Code=1R, ValueDisplayed=1R0
R42 R44 R47 R49 R67 R86 R87 R88 R98 R119: library part CMP-0022736-4, "RES, 100, 1%, 0.1 W, 0603", Manufacturer=Yageo, Power_W=100mW, Supplier Part Number 1=311-100HRCT-ND, TempCo="100 ppm/C", Tolerance_%=1%, Value2=0.1W, Value_Code=100R, ValueDisplayed=100
R62 R63: library part CMP-0022711-2, "RES, 2.20, 1%, 0.1 W, 0603", Manufacturer=Panasonic, Power_W=100mW, Supplier Part Number 1=P2.2AJCT-ND, TempCo="200 ppm/C", Tolerance_%=1%, Value2=0.1W, Value_Code=2R20, ValueDisplayed=1R0
R96: library part CMP-0022906-5, "RES, 20.0 k, 1%, 0.1 W, 0603", Manufacturer=Yageo, Power_W=100mW, Supplier Part Number 1=311-20.0KHRCT-ND, TempCo="100 ppm/C", Tolerance_%=1%, Value2=0.1W, Value_Code=20k0, ValueDisplayed=20.0k
TRAN1 TRAN2: library part Transformer_sec, "PQ32 TRANSFORMER", Manufacturer="YAXIN ELECTRONIC TECH"
U2 U3 U4 U10: library part CMP-0013393-6, "120-V, 3-A Peak, 5-V UVLO, 3x3, High-Frequency, High-Side/Low-Side Driver, DRC0010J (VSON-10)", Manufacturer="Texas Instruments", Rating=Catalog
U5 U6: library part CMP-0075733-4, "26-V, Bi-Directional, Zero-Drift, High Accuracy, Low-/High-Side, Voltage Out Current Shunt Monitor, DCK0006A (SOT-SC70-6)", Alternate Manufacturer="Texas Instruments", Alternate PartNumber=INA210BIDCKT, Operating Temperature Range="-40 to 125 C", Rating=Catalog
U20: library part CMP-0043733-1, "Low-Power Single Operational Amplifier, 3 to 30 V, -40 to 125 degC, 5-pin SOT23 (DBV5), Green (RoHS & no Sb/Br)", Manufacturer="Texas Instruments", Total Supply Voltage(Max)(+5V is 5, +/-5V is 10)=30, Total Supply Voltage(Min)(+5V is 5, +/-5V is 10)=3

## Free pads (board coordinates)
  oval 5x2 hole 1 slot 4 at 0 deg: 4(65.9,9)
  oval 4x2 hole 1 slot 3 at 0 deg: 4(66.963,48.6)
  oval 4x5 hole 3: 4(67.7,36.1) 5(67.8,22.9)
  oval 2x4 hole 1 slot 3 at 90 deg: 4(68.481,11.6) 4(68.7,46.4)
  rrect50% 2x1 smd: 8(68.746,6.73) 9(68.746,2.92) 10(68.746,5.46) 11(68.746,4.19)

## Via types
v1: diameter 0.559, hole 0.203, Top Layer to Bottom Layer, tented both sides, 490 vias
v2: diameter 0.559, hole 0.203, Top Layer to Bottom Layer, 14 vias
v3: diameter 0.7, hole 0.35, Top Layer to Bottom Layer, 4 vias
v4: diameter 0.762, hole 0.356, Top Layer to Bottom Layer, tented both sides, 1 vias

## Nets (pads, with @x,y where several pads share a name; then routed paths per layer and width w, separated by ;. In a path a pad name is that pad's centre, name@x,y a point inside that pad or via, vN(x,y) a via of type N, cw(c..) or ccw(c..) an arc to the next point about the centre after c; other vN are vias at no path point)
12Vo_A: C4.1 C7.1 C8.1 C9.1 C10.1 C11.1 C12.1 C13.1 C14.1 C15.1 C16.1 C101.1 C102.1 C103.1 C106.1 C137.1 Q1.5 Q1.6 Q1.7 Q1.8 Q1.9@33.189,46.772 Q2.5 Q2.6 Q2.7 Q2.8 Q2.9@52.063,41.133 Q4.5 Q4.6 Q4.7 Q4.8 Q4.9@52.063,46.772 Q5.5 Q5.6 Q5.7 Q5.8 Q5.9@33.276,35.493 Q7.5 Q7.6 Q7.7 Q7.8 Q7.9@33.189,41.133 Q8.5 Q8.6 Q8.7 Q8.8 Q8.9@52.063,35.493 R26.2 R29.2 R89.2 R92.2 R108.2 U5.4 | length 12.4
  Top Layer w0.254: R29.2@57.553,39.973 60.024,39.973 60.173,39.824 60.173,30.393 60.1,30.32 U5.4@59.875,30.32
  other v1: 35.993,33.036 36.501,33.036 58.483,33.05 58.991,33.05 35.993,34.294 36.501,34.294 58.483,34.308 58.991,34.308 35.993,35.551 36.501,35.551 58.483,35.565 58.991,35.565 35.993,36.808 36.501,36.808 58.483,36.822 58.991,36.822 35.993,38.066 36.501,38.066 58.483,38.08 58.991,38.08 35.993,39.323 36.501,39.323 58.483,39.337 58.991,39.337 35.993,40.581 36.501,40.581 58.483,40.595 58.991,40.595 36.068,41.706 36.576,41.706 58.483,41.72 58.991,41.72 36.068,42.964 36.576,42.964 58.483,42.978 58.991,42.978 36.068,44.221 36.576,44.221 58.483,44.235 58.991,44.235 36.068,45.479 36.576,45.479 58.483,45.492 58.991,45.492 36.068,46.736 36.576,46.736 58.483,46.75 58.991,46.75 36.068,47.993 36.576,47.993 58.483,48.007 58.991,48.007 36.068,49.251 36.576,49.251 58.483,49.265 58.991,49.265
12Vo_B: C25.1 C26.1 C27.1 C28.1 C29.1 C30.1 C31.1 C32.1 C33.1 C34.1 C35.1 C36.1 C37.1 C38.1 C39.1 C40.1 Q17.5 Q17.6 Q17.7 Q17.8 Q17.9@33.022,23.861 Q18.5 Q18.6 Q18.7 Q18.8 Q18.9@52.066,23.724 Q21.5 Q21.6 Q21.7 Q21.8 Q21.9@33.076,12.206 Q22.5 Q22.6 Q22.7 Q22.8 Q22.9@52.063,12.182 Q23.5 Q23.6 Q23.7 Q23.8 Q23.9@33.076,17.864 Q24.5 Q24.6 Q24.7 Q24.8 Q24.9@52.063,17.702 R56.2 R94.2 R97.2 R105.2 R117.2 U6.4 | length 13.4
  Top Layer w0.2: R117.2@57.675,18.696 59.846,18.696 60.024,18.518 60.024,8.303 59.727,8.005 U6.4@59.426,8.005
  other v1: 58.695,9.904 59.203,9.904 35.965,10.287 36.473,10.287 58.695,11.161 59.203,11.161 35.965,11.544 36.473,11.544 58.695,12.418 59.203,12.418 35.965,12.801 36.473,12.801 58.695,13.676 59.203,13.676 35.965,14.059 36.473,14.059 58.695,14.933 59.203,14.933 35.986,15.67 36.494,15.67 58.695,16.191 59.203,16.191 35.986,16.928 36.494,16.928 58.695,17.448 59.203,17.448 36.06,18.053 36.568,18.053 36.06,19.311 36.568,19.311 58.695,19.831 59.203,19.831 36.06,20.568 36.568,20.568 58.695,21.089 59.203,21.089 36.06,21.826 36.568,21.826 58.695,22.346 59.203,22.346 36.06,23.083 36.568,23.083 58.695,23.603 59.203,23.603 36.06,24.34 36.568,24.34 58.695,24.861 59.203,24.861 36.06,25.598 36.568,25.598 58.695,26.118 59.203,26.118
12Vout: pad.4@67.7,36.1 pad.5 R26.1 R29.1 R56.1 R89.1 R92.1 R94.1 R96.1 R97.1 R105.1 R108.1 R117.1 U5.5 U6.5 | length 51
  Top Layer w0.254: U6.5@59.399,7.328 59.804,7.328 59.854,7.378 59.858,7.378 60.078,7.599 60.078,7.602 60.451,7.975 60.451,18.411 60.737,18.696 R117.1@63.575,18.696 ; U5.5@59.875,29.67 59.948,29.743 60.356,29.743 60.627,30.014 60.627,39.727 60.873,39.973 R29.1@63.453,39.973
  Bottom Layer w0.254: R96.1@61.403,7.567 61.403,7.592 61.88,8.07 61.88,27.129 63.302,28.55 63.864,28.55 v4(63.868,28.554) ; pad.5@67.8,22.777 pad.5@67.8,22.9
  other v1: 64.561,17.669 65.061,17.669 65.598,17.668 64.55,18.194 65.05,18.194 65.587,18.193 64.55,18.702 65.05,18.702 65.587,18.701 64.55,19.21 65.05,19.21 65.587,19.209 64.55,19.798 65.049,19.798 65.587,19.797 64.55,20.306 65.049,20.306 65.587,20.305 64.55,20.814 65.049,20.814 65.587,20.813 64.55,21.322 65.049,21.322 65.587,21.321 64.549,21.91 65.049,21.91 65.587,21.909 64.549,22.418 65.049,22.418 65.587,22.417 64.549,22.926 65.049,22.926 65.587,22.925 64.549,23.434 65.049,23.434 65.587,23.433 64.539,23.959 65.038,23.959 65.576,23.958 64.539,24.467 65.038,24.467 65.576,24.466 64.538,25.055 65.038,25.055 65.575,25.054 64.538,25.563 65.038,25.563 65.575,25.562 64.538,26.071 65.038,26.071 65.575,26.07 64.538,26.579 65.038,26.579 65.575,26.578 64.409,31.245 64.909,31.245 65.446,31.244 64.409,31.753 64.909,31.753 65.446,31.752 64.409,32.341 64.909,32.341 65.446,32.34 64.409,32.849 64.909,32.849 65.446,32.848 64.409,33.357 64.909,33.357 65.446,33.356 64.409,33.865 64.909,33.865 65.446,33.864 64.398,34.39 64.898,34.39 65.435,34.389 64.398,34.898 64.898,34.898 65.435,34.897 64.398,35.486 64.897,35.486 65.435,35.485 64.398,35.994 64.897,35.994 65.435,35.993 64.398,36.502 64.897,36.502 65.435,36.501 64.398,37.01 64.897,37.01 65.435,37.009 64.387,37.535 64.886,37.535 65.424,37.534 64.387,38.043 64.886,38.043 65.424,38.042 64.386,38.631 64.886,38.631 65.424,38.63 64.386,39.139 64.886,39.139 65.424,39.138 64.386,39.647 64.886,39.647 65.424,39.646 64.386,40.155 64.886,40.155 65.424,40.154
LV_SW1A: C19.2 Q1.1 Q1.2 Q1.3 Q5.1 Q5.2 Q5.3 Q7.1 Q7.2 Q7.3 Q9.5 Q9.6 Q9.7 Q9.8 Q9.9@31.029,46.732 Q13.5 Q13.6 Q13.7 Q13.8 Q13.9@31.029,33.943 Q15.5 Q15.6 Q15.7 Q15.8 Q15.9@31.029,40.028 TRAN1.5 U10.5 | length 11.1
  Top Layer w0.254: TRAN1.5@25.997,32.333 25.997,31.918 27.804,30.111 28.22,30.111 30.328,28.002 C19.2@32.284,28.002 ; C19.2@32.258,28.194 32.308,28.244 33.463,28.244 33.955,27.753 U10.5@34.83,27.753
  other v1: 24.431,31.277 27.566,31.277 24.431,31.981 27.566,31.981 24.431,32.686 27.566,32.686 24.431,33.39 27.566,33.39 24.431,38.277 27.566,38.277 24.431,38.981 27.566,38.981 24.431,39.686 27.566,39.686 24.431,40.39 27.566,40.39 24.431,45.277 27.566,45.277 24.431,45.981 27.566,45.981 24.431,46.686 27.566,46.686 24.431,47.39 27.566,47.39
LV_SW1B: C20.2 Q2.1 Q2.2 Q2.3 Q4.1 Q4.2 Q4.3 Q8.1 Q8.2 Q8.3 Q10.5 Q10.6 Q10.7 Q10.8 Q10.9@49.903,40.337 Q12.5 Q12.6 Q12.7 Q12.8 Q12.9@49.903,46.732 Q16.5 Q16.6 Q16.7 Q16.8 Q16.9@49.903,33.943 TRAN1.6 U2.5 | length 10.3
  Top Layer w0.254: TRAN1.6@44.997,32.333 44.997,31.566 47.972,28.591 49.903,28.591 49.96,28.534 50.877,28.534 51.092,28.32 51.698,28.32 52.265,27.753 U2.5@52.902,27.753
  other v1: 43.431,31.277 46.566,31.277 43.431,31.981 46.566,31.981 43.431,32.686 46.566,32.686 43.431,33.39 46.566,33.39 43.431,38.277 46.566,38.277 43.431,38.981 46.566,38.981 43.431,39.686 46.566,39.686 43.431,40.39 46.566,40.39 43.431,45.277 46.566,45.277 43.431,45.981 46.566,45.981 43.431,46.686 46.566,46.686 43.431,47.39 46.566,47.39
LV_SW2A: C43.2 Q17.1 Q17.2 Q17.3 Q21.1 Q21.2 Q21.3 Q23.1 Q23.2 Q23.3 Q25.5 Q25.6 Q25.7 Q25.8 Q25.9@30.722,12.168 Q27.5 Q27.6 Q27.7 Q27.8 Q27.9@30.722,17.623 Q31.5 Q31.6 Q31.7 Q31.8 Q31.9@30.722,23.079 TRAN2.5 U3.5 | length 10.9
  Top Layer w0.25: TRAN2.5@27.413,10.612 27.413,10.13 27.807,9.736 28.227,9.736 28.56,9.403 28.56,5.96 30.378,4.142 C43.2@31.291,4.142 ; C43.2@31.488,4.08 U3.5@33.398,4.08
  Top Layer w1: C43.2@31.407,4.027 C43.2@31.407,4.162
  other v1: 24.431,10.612 27.566,10.612 24.431,11.316 27.566,11.316 24.431,12.02 27.566,12.02 24.431,12.724 27.566,12.724 24.431,17.612 27.566,17.612 24.431,18.316 27.566,18.316 24.431,19.02 27.566,19.02 24.431,19.724 27.566,19.724 24.431,24.612 27.566,24.612 24.431,25.316 27.566,25.316 24.431,26.02 27.566,26.02 24.431,26.724 27.566,26.724
LV_SW2B: C44.2 Q18.1 Q18.2 Q18.3 Q22.1 Q22.2 Q22.3 Q24.1 Q24.2 Q24.3 Q26.5 Q26.6 Q26.7 Q26.8 Q26.9@49.903,24.238 Q30.5 Q30.6 Q30.7 Q30.8 Q30.9@49.81,10.995 Q32.5 Q32.6 Q32.7 Q32.8 Q32.9@49.903,17.648 TRAN2.6 U4.5 | length 9.8
  Top Layer w0.254: C44.2@49.18,4.407 50.352,4.407 50.679,4.08 U4.5@51.502,4.08
  Top Layer w0.3: TRAN2.6@46.64,10.138 46.362,9.859 46.362,8.92 46.64,8.642 46.64,6.407 48.047,5 48.422,5 49.015,4.407 C44.2@49.18,4.407
  other v1: 43.431,10.612 46.566,10.612 43.431,11.316 46.566,11.316 43.431,12.02 46.566,12.02 43.431,12.724 46.566,12.724 43.431,17.612 46.566,17.612 43.431,18.316 46.566,18.316 43.431,19.02 46.566,19.02 43.431,19.724 46.566,19.724 43.431,24.612 46.566,24.612 43.431,25.316 46.566,25.316 43.431,26.02 46.566,26.02 43.431,26.724 46.566,26.724
NetC19_1: C19.1 U10.3 | length 3.3
  Top Layer w0.254: C19.1@31.607,29.724 C19.1@31.772,29.724 ; C19.1@32.258,30.226 32.545,29.939 33.29,29.939 34.477,28.753 U10.3@34.83,28.753
NetC20_1: C20.1 U2.3 | length 3.3
  Top Layer w0.254: C20.1@50.666,30.613 51.105,30.174 51.693,30.174 52.275,29.592 52.275,29.027 52.549,28.753 U2.3@52.902,28.753
NetC21_2: C21.2 R47.2 U10.8 | length 3.4
  Top Layer w0.254: U10.8@37.63,28.753 38.377,28.753 38.486,28.861 v1(38.555,28.861) ; v1@38.555,28.864 38.576,28.885 38.898,28.885 39.246,29.233 C21.2@39.246,29.258
  Bottom Layer w0.254: v1(38.555,28.861) 38.555,28.864 38.982,29.291 39.255,29.291 39.603,29.639 R47.2@39.603,29.664 ; R47.2@39.716,29.552 39.803,29.639 R47.2@39.803,29.664
NetC22_2: C22.2 R42.2 U10.7 | length 5.3
  Top Layer w0.254: U10.7@37.63,28.253 39.873,28.253 40.318,28.698 40.318,28.91 C22.2@40.666,29.258 41.524,29.258 41.599,29.333 v1(41.666,29.333)
  Bottom Layer w0.254: R42.2@41.115,29.664 41.446,29.333 v1(41.666,29.333)
NetC23_2: C23.2 R49.2 U2.8 | length 3.4
  Top Layer w0.254: U2.8@55.702,28.753 56.361,28.753 56.447,28.839 v1(56.514,28.839) 56.581,28.839 56.777,29.035 56.857,29.035 57.205,29.383 C23.2@57.205,29.408
  Bottom Layer w0.254: v1(56.514,28.839) 56.535,28.86 56.877,28.86 57.755,29.738 R49.2@57.78,29.738
NetC24_2: C24.2 R44.2 U2.7 | length 3.9
  Top Layer w0.254: U2.7@55.702,28.253 56.073,28.253 56.446,27.879 R44.2@57.358,27.879 57.383,27.879 57.731,28.227 57.731,28.252 58.22,28.741 58.22,29.086 C24.2@58.55,29.416
NetC43_1: C43.1 U3.3 | length 2.3
  Top Layer w0.254: C43.1@31.607,6.23 32.057,5.78 32.34,5.78 33.039,5.08 U3.3@33.398,5.08
NetC44_1: C44.1 U4.3 | length 2.9
  Top Layer w0.254: C44.1@49.18,6.439 49.659,5.96 50.167,5.96 51.047,5.08 U4.3@51.502,5.08
NetC45_2: C45.2 R87.2 U3.8 | length 3.8
  Top Layer w0.254: U3.8@36.198,5.08 36.916,5.08 37,5.164 v1(37.069,5.164)
  Bottom Layer w0.254: v1(37.069,5.164) 37.532,5.164 37.8,5.431 37.825,5.431 38.173,5.779 C45.2@38.173,5.804 R87.2@39.716,5.804
NetC46_2: C46.2 R67.2 U3.7 | length 4.6
  Top Layer w0.254: U3.7@36.198,4.58 36.551,4.58 36.757,4.374 37.883,4.374 38.31,4.801 C46.2@38.31,5.732 ; C46.2@38.32,5.743 R67.2@39.663,5.743
NetC47_2: C47.2 R88.2 U4.8 | length 3.9
  Top Layer w0.254: U4.8@54.302,5.08 54.991,5.08 v1(55.01,5.099)
  Bottom Layer w0.254: v1(55.01,5.099) 55.764,5.099 C47.2@55.895,5.23 55.895,5.255 56.243,5.603 56.268,5.603 57.079,6.413 57.079,6.482 R88.2@57.427,6.83
NetC48_2: C48.2 R86.2 U4.7 | length 5
  Top Layer w0.254: U4.7@54.302,4.58 54.672,4.58 54.759,4.493 55.261,4.493 55.272,4.503 55.577,4.503 56.055,4.981 56.055,5.687 C48.2@56.073,5.705 56.073,5.73 56.421,6.078 56.446,6.078 57.3,6.932 57.327,6.932 57.675,7.28 R86.2@57.675,7.305
NetQ1_4: Q1.4 Q5.4 Q7.4 R31.2 | length 18
  Top Layer w0.254: Q7.4@29.289,39.228 30.36,39.228 30.445,39.313 ; Q1.4@29.289,44.867 29.399,44.758 29.837,44.758 30.445,44.15 30.445,39.313 ; Q5.4@29.376,33.588 30.445,33.588 ; 30.433,38.592 30.445,38.581 ; 30.445,32.718 30.445,33.588 ; 30.445,32.718 30.445,31.318 R31.2@30.43,31.303 30.43,32.703 30.445,32.718 ; 30.445,33.588 30.445,38.581 ; 30.445,38.581 30.445,39.313
NetQ2_4: Q2.4 Q4.4 Q8.4 R34.2 | length 15.9
  Top Layer w0.254: Q8.4@48.163,33.588 48.22,33.532 48.765,33.532 48.917,33.379 ; Q2.4@48.163,39.228 48.17,39.222 48.815,39.222 48.92,39.116 ; Q4.4@48.163,44.867 48.276,44.754 48.708,44.754 48.92,44.542 48.92,39.116 ; R34.2@48.917,31.134 48.917,32.247 48.917,33.379 ; 48.917,33.379 48.92,33.383 48.92,39.116
NetQ9_4: Q9.4 Q13.4 Q15.4 R36.2 | length 17.1
  Bottom Layer w0.254: Q15.4@34.929,38.123 34.007,38.123 ; Q9.4@34.929,44.827 34.87,44.767 34.332,44.767 34.007,44.443 34.007,38.123 ; R36.2@36.399,31.142 36.374,31.167 35.423,31.167 35.232,31.358 35.232,31.91 35.104,32.038 34.754,32.038 34.007,32.785 34.007,38.123
NetQ10_4: Q10.4 Q12.4 Q16.4 R39.2 | length 16.4
  Bottom Layer w0.254: Q10.4@53.803,38.432 52.892,38.432 ; Q12.4@53.803,44.827 53.756,44.779 53.194,44.779 52.892,44.478 52.892,38.432 ; R39.2@55,31.884 54.255,31.884 54.23,31.91 53.931,31.91 Q16.4@53.803,32.038 53.743,32.098 53.206,32.098 52.892,32.412 52.892,38.432
NetQ17_4: Q17.4 Q21.4 Q23.4 R58.2 | length 17.7
  Top Layer w0.254: Q17.4@29.122,21.956 29.198,21.88 29.703,21.88 30.279,21.303 30.279,15.953 ; Q21.4@29.176,10.301 30.202,10.301 30.279,10.224 ; Q23.4@29.176,15.959 30.273,15.959 30.279,15.953 ; R58.2@31.578,7.823 31.553,7.823 31.205,8.171 31.205,8.196 30.279,9.121 30.279,10.224 ; 30.279,10.224 30.279,15.953
NetQ18_4: Q18.4 Q22.4 Q24.4 R59.2 | length 16.4
  Top Layer w0.254: Q22.4@48.163,10.277 49.121,10.277 ; Q24.4@48.163,15.797 49.121,15.797 ; Q18.4@48.166,21.819 48.294,21.691 48.68,21.691 49.121,21.251 49.121,15.797 ; R59.2@49.347,8.059 49.121,8.285 49.121,10.277 ; 49.121,10.277 49.121,15.797
NetQ25_4: Q25.4 Q27.4 Q31.4 R62.2 | length 15.8
  Bottom Layer w0.254: R62.2@33.966,7.662 33.991,7.662 34.339,8.01 34.339,8.035 34.622,8.317 Q25.4@34.622,10.263 34.447,10.263 34.319,10.391 34.319,10.566 33.769,11.116 33.769,15.718 ; Q27.4@34.622,15.718 33.769,15.718 ; Q31.4@34.622,21.174 34.567,21.12 34.019,21.12 33.769,20.87 33.769,15.718
NetQ26_4: Q26.4 Q30.4 Q32.4 R63.2 | length 17.2
  Bottom Layer w0.254: R63.2@52.092,7.404 52.117,7.404 52.465,7.752 52.465,7.845 53.407,8.787 53.407,8.962 53.535,9.09 Q30.4@53.71,9.09 ; Q30.4@53.385,9.24 52.892,9.733 52.892,15.734 ; Q32.4@53.803,15.743 52.9,15.743 52.892,15.734 ; Q26.4@53.803,22.333 53.675,22.205 53.362,22.205 52.892,21.735 52.892,15.734
NetR23_2: R23.2 R96.2 R98.1 | length 17.8
  Layer 2 w0.254: v1(49.548,3.102) 49.969,3.524 53.153,3.524 53.973,4.343 54.071,4.343 54.085,4.358 54.963,4.358 54.977,4.343 55.951,4.343 56.433,4.826 59.19,4.826 v1(59.781,4.235)
  Bottom Layer w0.254: R98.1@48.338,4.679 48.492,4.524 49.07,4.524 49.53,4.064 49.53,3.12 v1(49.548,3.102) ; v1(59.781,4.235) 59.723,4.294 59.723,4.435 59.301,4.857 59.276,4.857 58.928,5.205 58.928,5.255 59.276,5.603 59.301,5.603 59.665,5.967 R96.2@61.403,5.967
NetR118_1: R118.1 R119.2 U20.3 | length 3.9
  Bottom Layer w0.254: U20.3@65.7,4.679 67.001,4.679 67.349,5.027 67.349,5.171 68.108,5.93 68.133,5.93 R118.1@68.228,6.025 ; R118.1@68.402,6.328 68.402,6.303 68.228,6.129 R118.1@68.228,6.025 ; R118.1@68.481,6.303 68.481,6.278 R118.1@68.228,6.025
PB_3V3-s: C49.1 C50.1 C60.2 J7.12 pad.8 R118.2 U5.3 U6.3 U20.5 | length 57.2
  Top Layer w0.2: U6.3@61.576,7.905 62.157,7.905 v1@62.496,7.566 ; v1@62.549,7.513 62.549,7.039 C50.1@62.654,6.934
  Top Layer w0.254: U5.3@62.125,30.32 62.152,30.347 62.152,30.86 v1(62.179,30.887) ; C50.1@62.654,6.934 C50.1@62.758,6.934 ; C50.1@62.758,6.83 62.894,6.965 68.511,6.965 pad.8@68.746,6.73
  Layer 1 w0.254: v1(62.179,30.887) 62.237,30.829 62.469,30.829 62.656,30.641 62.656,28.085 62.334,27.763 62.334,4.502 63.146,3.691 v1(63.146,3.608)
  Layer 2 w0.254: J7.12@54.26,1.2 54.26,2.24 54.497,2.477 62.357,2.477 63.104,3.224 63.104,3.566 v1(63.146,3.608)
  Bottom Layer w0.254: C49.1@61.198,31.024 61.564,31.39 61.676,31.39 61.676,31.037 61.689,31.024 61.959,31.024 62.096,30.887 v1(62.179,30.887) ; v1(62.523,7.592) 63.029,7.086 63.029,6.7 U20.5@63.15,6.579 ; v1(63.146,3.608) 63.756,3.608 C60.2@63.993,3.371 64.018,3.371 64.366,3.023 64.366,2.998 64.795,2.569 67.064,2.569 68.466,3.97 68.466,4.688 R118.2@68.481,4.703
PB_AGND-s: C49.2 C50.2 C54.2 C55.1 C56.1 C60.1 J7.18 R23.1 R119.1 U5.2 U6.2 U20.2 | length 62.6
  Top Layer w0.254: J7.18@46.64,1.2 46.71,1.27 46.71,1.903 47.043,2.237 59.762,2.237 61.481,3.955 ; v1(61.199,29.75) 61.206,29.743 62.052,29.743 U5.2@62.125,29.67 ; U6.2@61.576,7.255 60.796,7.255 60.332,6.791 v1(60.332,6.765) 60.332,6.145 59.929,5.742 59.929,5.717 59.581,5.369 59.556,5.369 59.57,5.356 59.57,5.319 60.332,4.556 60.332,4.489 60.866,3.955 61.481,3.955 ; v1(64.561,5.603) 64.535,5.629 63.255,5.629 63.229,5.603 63.106,5.603 62.758,5.255 62.758,5.205 62.41,4.857 62.383,4.857 61.481,3.955
  Layer 1 w0.254: v1(60.332,6.765) 60.917,7.35 60.917,26.87 60.463,27.324 60.463,29.013 v1(61.199,29.75)
  Bottom Layer w0.254: J7.18@46.698,0.841 C54.2@46.698,3.048 ; R23.1@58.928,6.83 60.199,6.83 60.264,6.765 v1(60.332,6.765) ; C49.2@59.716,31.372 C49.2@59.724,31.364 ; C55.1@59.724,30.089 C55.1@60.064,29.75 ; C60.1@65.593,3.371 65.568,3.371 65.22,3.719 65.22,3.744 64.561,4.403 v1(64.561,5.603) 64.587,5.629 U20.2@65.7,5.629 66.351,5.629 66.628,5.906 66.653,5.906 67.001,6.254 R119.1@67.001,6.279
  Bottom Layer w0.508: C55.1@59.724,30.089 C49.2@59.724,31.364 ; C55.1@60.064,29.75 v1(61.199,29.75)
PB_CT1+: CSTs.1 J7.22 | length 38.6
  Layer 1 w0.254: CSTs.1@19.431,23.876 20.643,23.876 23.322,21.197 v3(23.322,21.123) 23.322,9.08 30.847,1.555 41.014,1.555 41.369,1.2 J7.22@41.56,1.2
PB_CT1-: CSTs.2 J7.21 | length 42.9
  Layer 1 w0.254: v3(23.322,22.218) 23.999,21.541 23.999,20.842 23.781,20.624 23.781,14.967 23.776,14.962 23.776,9.268 31.035,2.009 36.421,2.009 36.514,2.102 42.359,2.102 42.678,1.783 42.678,1.352 J7.21@42.83,1.2
  Layer 2 w0.254: CSTs.2@17.431,23.876 17.631,23.676 17.631,23.232 18.257,22.606 22.934,22.606 v3(23.322,22.218)
PB_CT2+: CSTs.3 J7.20 | length 48.4
  Layer 1 w0.254: v3(23.322,23.34) 23.443,23.34 23.617,23.166 23.674,23.166 24.027,22.812 29.105,22.812 30.027,21.891 30.027,8.594 32.08,6.541 32.08,4.437 34.054,2.463 36.233,2.463 36.364,2.594 43.309,2.594 44.015,1.888 44.015,1.285 J7.20@44.1,1.2
  Layer 2 w0.254: CSTs.3@15.431,23.876 16.447,24.892 21.768,24.892 23.32,23.34 v3(23.322,23.34)
PB_CT2-: CSTs.4 J7.19 | length 52.3
  Layer 1 w0.254: CSTs.4@13.431,23.876 14.45,24.895 22.95,24.895 23.207,24.638 v3(23.322,24.638) 23.407,24.553 23.407,24.212 24.353,23.266 29.363,23.266 30.481,22.149 30.481,8.782 32.534,6.729 32.534,4.625 34.242,2.917 36.045,2.917 36.176,3.048 44.866,3.048 45.305,2.609 45.305,1.265 J7.19@45.37,1.2
PB_ISEC1: J7.15 U5.6 | length 40.5
  Top Layer w0.254: J7.15@50.45,1.2 J7.15@50.603,1.352 ; U5.6@59.875,29.02 59.875,28.528 60.637,27.766 v1(61.524,27.766)
  Layer 1 w0.254: v1(61.524,27.766) 61.524,27.683 61.676,27.531 61.676,27.53 61.838,27.368 61.838,4.088 v1(62.215,3.711)
  Layer 2 w0.254: J7.15@50.45,1.2 50.603,1.352 50.603,1.757 51.915,3.07 53.341,3.07 54.159,3.887 54.257,3.887 54.273,3.904 54.775,3.904 54.791,3.887 55.372,3.887 55.917,3.342 61.846,3.342 v1(62.215,3.711)
PB_ISEC2: J7.14 U6.6 | length 14.4
  Top Layer w0.254: v1(50.523,2.917) 50.591,2.917 50.824,3.151 51.949,3.151 52.306,2.794 54.154,2.794 54.257,2.691 54.791,2.691 54.895,2.794 57.249,2.794 58.695,4.24 58.695,6.28 58.947,6.532 59.253,6.532 U6.6@59.326,6.605
  Bottom Layer w0.254: v1(50.523,2.917) 50.526,2.914 50.946,2.914 51.568,2.293 51.568,1.352 J7.14@51.72,1.2
PB_URAT2_RX: J7.3 pad.10 | length 6.3
  Top Layer w0.254: J7.3@65.69,1.2 66.727,2.237 66.727,4.556 67.514,5.343 68.636,5.343 pad.10@68.746,5.454 ; pad.10@68.746,5.53 pad.10@68.834,5.53
PB_URAT2_TX: J7.2 pad.11 | length 4.5
  Top Layer w0.254: J7.2@66.96,1.2 67.113,1.352 67.113,1.678 67.181,1.747 67.181,3.88 67.478,4.177 pad.11@68.746,4.177
PB_VPRI: J7.17
PB_VSEC: C54.1 J7.16 R98.2 | length 4.6
  Bottom Layer w0.254: R98.2@46.738,4.679 46.763,4.679 47.111,4.331 47.111,4.21 48.411,2.91 48.545,2.91 48.719,2.736 48.719,2.711 49.18,2.251 J7.16@49.18,1.2
SR1_AH: J7.11 R42.1 | length 56
  Layer 1 w0.254: v1(41.047,27.341) 40.566,27.822 40.13,27.822 39.877,28.075 32.69,28.075 31.389,26.774 31.389,10.507 35.982,5.914 48.994,5.914 52.651,2.257 54.048,2.257 54.085,2.221 55.257,2.221 55.521,1.957 55.521,1.21 J7.11@55.53,1.2
  Bottom Layer w0.254: v1(41.047,27.341) 41.047,27.995 R42.1@41.115,28.064
SR1_AL: J7.10 R47.1 | length 53.7
  Layer 1 w0.254: v1(38.898,27.468) 38.816,27.468 38.683,27.601 32.858,27.601 31.843,26.586 31.843,10.695 36.17,6.368 49.182,6.368 52.839,2.711 54.236,2.711 54.273,2.675 54.775,2.675 54.812,2.711 55.543,2.711 56.541,1.714 56.541,1.675 56.8,1.415 J7.10@56.8,1.2
  Bottom Layer w0.254: v1(38.898,27.468) 38.898,27.535 39.054,27.691 39.455,27.691 R47.1@39.832,28.068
